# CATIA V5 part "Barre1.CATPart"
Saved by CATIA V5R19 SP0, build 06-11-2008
Part number: Barre1
Bounding box of the stored display mesh (mm): x -42.5 to 42.5, y -50 to 50, z -2.5 to 2.5
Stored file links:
  F:\IAO\Catia\Barre1.CATPart
  F:\IAO\Catia\Etau.CATProduct
  F:\IAO\Catia\Squelette_Barre1.CATPart
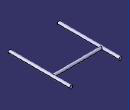
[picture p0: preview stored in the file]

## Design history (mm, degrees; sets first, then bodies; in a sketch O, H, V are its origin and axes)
Set1
  Point1: linked copy from another document
  Point2: linked copy from another document
Body1 (main body)
  Sketch1 on zx-plane, origin (0, 0, 0), H (-1, 0, 0), V (0, 0, 1)
    circle A1 centre (40, 0) radius 2.5
    point P1 (40, 0)
    circle A2 centre (-40, 0) radius 2.5
    point P2 (-40, 0)
    reference projected point E1 (40, 0) from Point1
    reference projected point E2 (-40, 0) from Point2
    radius A2 = 2.5
    radius A1 = 2.5
    coincidence: P1 E1, P2 E2
  Pad1: profile Sketch1, direction (0, 1, 0), length 50, mirrored extent
  Sketch2 on yz-plane, origin (0, 0, 0), H (0, 1, 0), V (0, 0, 1)
    circle A1 centre (20, 0) radius 2.5
    point P1 (20, 0)
    radius A1 = 2.5
    distance P1 V = 20
    coincidence: P1 H
  Pad2: profile Sketch2, direction (1, 0, 0), length 39, mirrored extent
